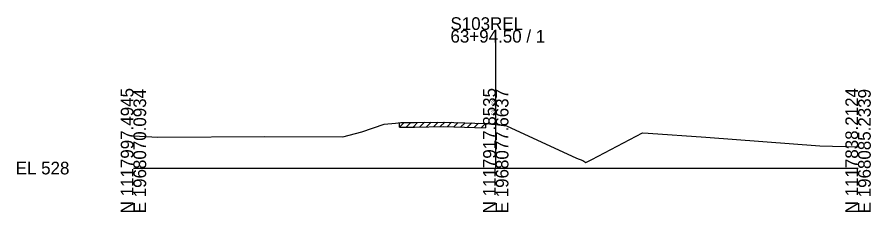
# Model space of a CAD drawing. Extents: x -26 to 163, y -10 to 24518.
# Drawn here: x -25.7 to 162.8, y 11490.3 to 11533.4 of the extents above; entities that cross this region are included whole.
import ezdxf

# ---------------------------------------------------------------- set-up
doc = ezdxf.new("R2010")
doc.units = 0
for name, color, linetype in [('RD_GPK_XS_Cell', 7, 'Continuous'), ('RD_XS_ExGround', 7, 'Continuous'), ('RD_XS_ExPaveRet', 7, 'Continuous'), ('RD_XS_TX_Elev_EX', 7, 'Continuous')]:
    doc.layers.add(name, color=color, linetype=linetype)

msp = doc.modelspace()

# ---------------------------------------------------------------- linework, layer by layer
at = {"layer": 'RD_GPK_XS_Cell'}
for p, q in [((80, 11500), (80, 11530.53)), ((0, 11500), (80, 11500)), ((80, 11500), (160, 11500))]:
    msp.add_line(p, q, dxfattribs=at)
at = {"layer": 'RD_XS_ExGround'}
msp.add_lwpolyline([(0, 11507.13), (5.41, 11506.85), (28.98, 11506.95), (46.26, 11506.87), (50.44, 11508.02), (55.39, 11509.69), (57.83, 11509.93), (59.03, 11510.06), (62.05, 11510.07), (68.45, 11510.18), (75.37, 11509.96), (78.03, 11509.84), (79.22, 11509.73), (80, 11509.63), (82.36, 11509.34), (97.83, 11502.2), (99.21, 11501.65), (99.88, 11501.23), (101.2, 11501.87), (112.4, 11507.77), (113.64, 11507.74), (126.36, 11506.84), (151.59, 11504.91), (160, 11504.66)], dxfattribs=at)
at = {"layer": 'RD_XS_ExPaveRet'}
for p, q in [((58.72, 11509.02), (59.76, 11510.06)), ((58.72, 11509.02), (58.72, 11510.02)), ((60.22, 11509.06), (61.23, 11510.07)), ((61.73, 11509.07), (62.74, 11510.08)), ((63.23, 11509.09), (64.25, 11510.11)), ((64.73, 11509.11), (65.75, 11510.13)), ((66.23, 11509.14), (67.25, 11510.16)), ((67.74, 11509.17), (68.74, 11510.17)), ((69.24, 11509.15), (70.21, 11510.12)), ((70.74, 11509.1), (71.72, 11510.07)), ((72.25, 11509.06), (73.22, 11510.03)), ((73.75, 11509.01), (74.72, 11509.98)), ((75.25, 11508.96), (76.22, 11509.92)), ((58.72, 11509.02), (59.03, 11509.06)), ((59.03, 11509.06), (62.05, 11509.07)), ((62.05, 11509.07), (68.45, 11509.18)), ((68.45, 11509.18), (75.37, 11508.96)), ((75.37, 11508.96), (77.73, 11508.86)), ((76.76, 11508.9), (77.72, 11509.86)), ((77.73, 11509.86), (77.73, 11508.86))]:
    msp.add_line(p, q, dxfattribs=at)

# ---------------------------------------------------------------- texts
at = {"layer": 'RD_GPK_XS_Cell'}
for s, p in [('S103REL', (70, 11530.53)), ('63+94.50 / 1', (70, 11527.73)), ('EL 528', (-26, 11498.6))]:
    msp.add_text(s, height=2.8, dxfattribs=at).set_placement(p)
for s, p in [('N 1117997.4945', (0, 11490)), ('N 1117917.8535', (80, 11490)), ('N 1117838.2124', (160, 11490)), ('E 1968070.0934', (2.8, 11490)), ('E 1968077.6637', (82.8, 11490)), ('E 1968085.2339', (162.8, 11490))]:
    msp.add_text(s, height=2.8, rotation=90, dxfattribs=at).set_placement(p)
at = {"layer": 'RD_XS_TX_Elev_EX'}
msp.add_text('537.63', height=0.8, rotation=90, dxfattribs=at).set_placement((79.9, 11511.63))

doc.saveas('drawing.dxf')
